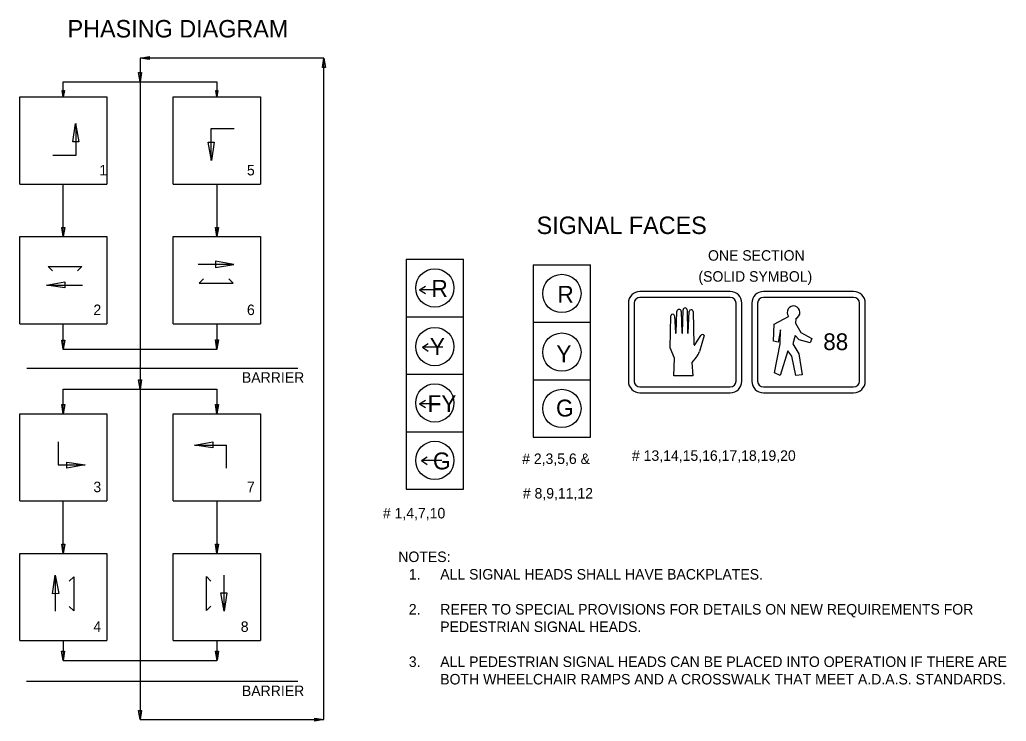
# Model space of a CAD drawing. Extents: x 1 to 35.4, y 0.4 to 10.6.
# Drawn here: x 26.82 to 34.35, y 5.23 to 10.58 of the extents above; entities that cross this region are included whole.
import ezdxf

# ---------------------------------------------------------------- set-up
doc = ezdxf.new("R2010")
doc.units = 0
for name, color, linetype in [('$', 7, 'Continuous'), ('base', 7, 'Continuous'), ('PHASE', 7, 'Continuous'), ('TBLBDR', 7, 'Continuous'), ('TBLTEXT', 7, 'Continuous'), ('TITEXT', 7, 'Continuous')]:
    doc.layers.add(name, color=color, linetype=linetype)

msp = doc.modelspace()

# ---------------------------------------------------------------- linework, layer by layer
at = {"layer": '$'}
for p, q in [((27.1527, 10.1019), (28.3243, 10.1019)), ((28.454, 8.7083), (28.1808, 8.7083)), ((27.025, 8.551), (27.2981, 8.551)), ((27.1147, 7.3563), (27.1147, 7.1812)), ((28.1534, 7.3322), (28.3967, 7.3322)), ((28.3967, 7.1577), (28.3967, 7.3322)), ((27.1147, 7.1812), (27.3197, 7.1812)), ((27.1527, 5.8427), (27.1527, 5.6899))]:
    msp.add_line(p, q, dxfattribs=at)
for points in [[(29.1404, 10.282), (27.7385, 10.282), (27.7385, 10.1019)], [(27.7385, 5.7278), (27.7385, 5.2395), (29.1404, 5.2395), (29.1404, 10.282)], [(27.1527, 9.987), (27.1527, 10.1019)], [(28.3243, 10.1019), (28.3243, 9.987)], [(27.2484, 9.7833), (27.2484, 9.5401), (27.0739, 9.5401)], [(28.2818, 9.5015), (28.2818, 9.7448), (28.4563, 9.7448)], [(27.1527, 8.9222), (27.1527, 9.3225)], [(28.3243, 9.3225), (28.3243, 8.9222)], [(28.3243, 8.2577), (28.3243, 8.0617), (27.1527, 8.0617), (27.1527, 8.2577)], [(27.7385, 8.0617), (27.7385, 7.7592)], [(27.1527, 7.572), (27.1527, 7.7592), (28.3243, 7.7592), (28.3243, 7.572)], [(27.1527, 6.5072), (27.1527, 6.9075)], [(28.3243, 6.9075), (28.3243, 6.5072)], [(27.0919, 6.34), (27.0919, 6.0669)], [(28.3795, 6.0669), (28.3795, 6.34)]]:
    msp.add_lwpolyline(points, dxfattribs=at)
at = {"layer": 'PHASE'}
for p, q in [((29.8702, 8.5159), (29.9152, 8.5442)), ((30.0263, 8.5159), (29.8702, 8.5159)), ((29.8702, 8.5159), (29.9152, 8.4875)), ((29.8917, 8.078), (29.9366, 8.1063)), ((30.0478, 8.078), (29.8917, 8.078)), ((29.8917, 8.078), (29.9366, 8.0496)), ((29.8695, 7.6472), (29.9144, 7.6755)), ((30.0256, 7.6472), (29.8695, 7.6472)), ((29.8695, 7.6472), (29.9144, 7.6188)), ((29.8844, 7.2141), (29.9293, 7.2424)), ((30.0405, 7.2141), (29.8844, 7.2141)), ((29.8844, 7.2141), (29.9293, 7.1857))]:
    msp.add_line(p, q, dxfattribs=at)
for points in [[(31.8754, 8.1885), (31.88, 8.364)], [(31.9106, 8.3643), (31.9146, 8.1878)], [(31.9794, 8.0023), (31.9477, 7.9631), (31.9556, 7.8601), (31.809, 7.8601), (31.8142, 7.9949), (31.7812, 8.0742), (31.7864, 8.3182)], [(31.8147, 8.3185), (31.822, 8.1884)], [(31.8261, 8.1884), (31.8319, 8.3506)], [(31.8665, 8.3517), (31.871, 8.1884)], [(31.9188, 8.1878), (31.9275, 8.3506)], [(31.9564, 8.3517), (31.9627, 8.0985)], [(32.6217, 7.8627), (32.5777, 7.8825), (32.6202, 8.1041), (32.622, 8.21), (32.6064, 8.1182), (32.5697, 8.1239), (32.5759, 8.2545), (32.6847, 8.3136)], [(32.7393, 8.2983), (32.7384, 8.2617), (32.7793, 8.1904), (32.8617, 8.1458), (32.8496, 8.1128), (32.7654, 8.1341), (32.7359, 8.1673), (32.7179, 8.1044), (32.7638, 8.0292), (32.7877, 7.8678), (32.741, 7.864), (32.7104, 8.0102), (32.6802, 8.0499), (32.6217, 7.8627)], [(31.9704, 8.0959), (32.0156, 8.1685)], [(32.0417, 8.1691), (32.0056, 8.0454)]]:
    msp.add_lwpolyline(points, dxfattribs=at)
for centre in [(29.9865, 8.5306), (30.9555, 8.4883), (29.9865, 8.0834), (30.9555, 8.041), (29.9865, 7.654), (30.9555, 7.6116), (29.9865, 7.2156)]:
    msp.add_circle(centre, 0.1461, dxfattribs=at)
for centre, radius, start, end in [((31.8492, 8.3489), 0.0175, 9.19884, 174.46931), ((31.8953, 8.3624), 0.0154, 6.92087, 174.32546), ((31.942, 8.3504), 0.0145, 5.08526, 179.16231), ((32.7227, 8.3443), 0.0489, 289.8249, 219.00652), ((31.8006, 8.3177), 0.0142, 3.29515, 178.19589), ((31.8241, 8.1884), 0.00203, 181.1546, 359.79185), ((31.8732, 8.1885), 0.0022, 181.28856, 2.11272), ((31.9167, 8.188), 0.00213, 183.88454, 355.84434), ((32.0289, 8.1587), 0.0165, 38.81604, 143.75147), ((31.9671, 8.0988), 0.00441, 183.95836, 317.86458), ((31.9141, 8.0715), 0.0951, 313.34065, 344.09332)]:
    msp.add_arc(centre, radius, start, end, dxfattribs=at)
at = {"layer": 'TBLBDR'}
for p, q in [((26.8205, 9.987), (27.485, 9.987)), ((26.8205, 9.3225), (26.8205, 9.987)), ((27.485, 9.987), (27.485, 9.3225)), ((27.992, 9.987), (28.6565, 9.987)), ((27.992, 9.3225), (27.992, 9.987)), ((28.6565, 9.987), (28.6565, 9.3225)), ((26.8205, 9.3225), (27.485, 9.3225)), ((27.992, 9.3225), (28.6565, 9.3225)), ((26.8205, 8.9222), (27.485, 8.9222)), ((26.8205, 8.2577), (26.8205, 8.9222)), ((27.485, 8.9222), (27.485, 8.2577)), ((27.992, 8.2577), (27.992, 8.9222)), ((27.992, 8.9222), (28.6565, 8.9222)), ((28.6565, 8.9222), (28.6565, 8.2577)), ((29.7673, 8.7498), (30.2056, 8.7498)), ((29.7673, 8.7498), (29.7673, 6.9964)), ((30.2056, 6.9964), (30.2056, 8.7498)), ((30.7363, 8.7075), (31.1747, 8.7075)), ((30.7363, 8.7075), (30.7363, 7.3924)), ((31.1747, 7.3924), (31.1747, 8.7075)), ((29.7673, 8.3115), (30.2056, 8.3115)), ((26.8205, 8.2577), (27.485, 8.2577)), ((27.992, 8.2577), (28.6565, 8.2577)), ((30.7363, 8.2691), (31.1747, 8.2691)), ((29.7673, 7.8731), (30.2056, 7.8731)), ((30.7363, 7.8308), (31.1747, 7.8308)), ((26.8205, 7.572), (27.485, 7.572)), ((26.8205, 6.9075), (26.8205, 7.572)), ((27.485, 7.572), (27.485, 6.9075)), ((27.992, 7.572), (28.6565, 7.572)), ((27.992, 6.9075), (27.992, 7.572)), ((28.6565, 7.572), (28.6565, 6.9075)), ((29.7673, 7.4348), (30.2056, 7.4348)), ((30.7363, 7.3924), (31.1747, 7.3924)), ((29.7673, 6.9964), (30.2056, 6.9964)), ((26.8205, 6.9075), (27.485, 6.9075)), ((27.992, 6.9075), (28.6565, 6.9075)), ((26.8205, 5.8427), (26.8205, 6.5072)), ((26.8205, 6.5072), (27.485, 6.5072)), ((27.485, 6.5072), (27.485, 5.8427)), ((27.992, 5.8427), (27.992, 6.5072)), ((27.992, 6.5072), (28.6565, 6.5072)), ((28.6565, 6.5072), (28.6565, 5.8427)), ((26.8205, 5.8427), (27.485, 5.8427)), ((27.992, 5.8427), (28.6565, 5.8427))]:
    msp.add_line(p, q, dxfattribs=at)
for points in [[(32.2397, 8.5032), (31.5514, 8.5032)], [(33.1811, 8.5032), (32.4929, 8.5032)], [(32.2397, 8.4589), (31.5514, 8.4589)], [(33.1811, 8.4589), (32.4929, 8.4589)], [(31.4627, 8.4145), (31.4627, 7.82)], [(31.5071, 8.4145), (31.5071, 7.82)], [(32.284, 7.82), (32.284, 8.4145)], [(32.3284, 7.82), (32.3284, 8.4145)], [(32.4041, 8.4145), (32.4041, 7.82)], [(32.4485, 8.4145), (32.4485, 7.82)], [(33.2255, 7.82), (33.2255, 8.4145)], [(33.2698, 7.82), (33.2698, 8.4145)], [(31.5514, 7.7757), (32.2397, 7.7757)], [(32.4929, 7.7757), (33.1811, 7.7757)], [(31.5514, 7.7313), (32.2397, 7.7313)], [(32.4929, 7.7313), (33.1811, 7.7313)]]:
    msp.add_lwpolyline(points, dxfattribs=at)
for centre, radius, start, end in [((31.5514, 8.4145), 0.0887, 90, 180), ((32.2397, 8.4145), 0.0887, 360, 90), ((32.4929, 8.4145), 0.0887, 90, 180), ((33.1811, 8.4145), 0.0887, 360, 90), ((31.5514, 8.4145), 0.0444, 90, 180), ((32.2397, 8.4145), 0.0444, 360, 90), ((32.4929, 8.4145), 0.0444, 90, 180), ((33.1811, 8.4145), 0.0444, 360, 90), ((31.5514, 7.82), 0.0887, 180, 270), ((31.5514, 7.82), 0.0444, 180, 270), ((32.2397, 7.82), 0.0887, 270, 360), ((32.2397, 7.82), 0.0444, 270, 360), ((32.4929, 7.82), 0.0887, 180, 270), ((32.4929, 7.82), 0.0444, 180, 270), ((33.1811, 7.82), 0.0887, 270, 360), ((33.1811, 7.82), 0.0444, 270, 360)]:
    msp.add_arc(centre, radius, start, end, dxfattribs=at)
at = {"layer": 'TITEXT'}
for p, q in [((26.8752, 7.92), (28.9411, 7.92)), ((28.3243, 5.8427), (28.3243, 5.6899)), ((27.1527, 5.6899), (28.3243, 5.6899)), ((28.9411, 5.5313), (26.8732, 5.5313))]:
    msp.add_line(p, q, dxfattribs=at)
for points in [[(27.8083, 10.2949), (27.8087, 10.2716), (27.7385, 10.282)], [(29.1533, 10.2122), (29.13, 10.2118), (29.1404, 10.282)], [(27.7256, 10.1717), (27.749, 10.1721), (27.7385, 10.1019)], [(27.1446, 10.0361), (27.1609, 10.0361), (27.1527, 9.987)], [(28.3161, 10.0361), (28.3325, 10.0361), (28.3243, 9.987)], [(27.2725, 9.6442), (27.2258, 9.6434), (27.2467, 9.7839)], [(28.2576, 9.6407), (28.3043, 9.6415), (28.2834, 9.501)], [(27.1411, 8.9923), (27.1644, 8.9923), (27.1527, 8.9222)], [(28.3126, 8.9923), (28.336, 8.9923), (28.3243, 8.9222)], [(28.3143, 8.7341), (28.3135, 8.6874), (28.454, 8.7083)], [(27.1646, 8.5769), (27.1654, 8.5302), (27.025, 8.551)], [(27.1411, 8.1333), (27.1644, 8.1333), (27.1527, 8.0633)], [(28.3126, 8.1349), (28.336, 8.1349), (28.3243, 8.0649)], [(27.7257, 7.829), (27.749, 7.8294), (27.7386, 7.7592)], [(27.1411, 7.642), (27.1644, 7.642), (27.1527, 7.572)], [(28.3126, 7.642), (28.336, 7.642), (28.3243, 7.572)], [(28.293, 7.358), (28.2939, 7.3113), (28.1534, 7.3322)], [(27.18, 7.1554), (27.1792, 7.2021), (27.3197, 7.1812)], [(27.1411, 6.5772), (27.1644, 6.5772), (27.1527, 6.5072)], [(28.3126, 6.5772), (28.336, 6.5772), (28.3243, 6.5072)], [(27.1177, 6.2004), (27.071, 6.1996), (27.0919, 6.34)], [(28.3537, 6.2065), (28.4004, 6.2074), (28.3795, 6.0669)], [(27.1398, 5.7604), (27.1632, 5.7608), (27.1527, 5.6906)], [(28.3126, 5.7604), (28.336, 5.7608), (28.3255, 5.6906)], [(27.7256, 5.3093), (27.749, 5.3098), (27.7385, 5.2395)], [(29.0707, 5.2273), (29.0703, 5.2506), (29.1405, 5.2402)]]:
    msp.add_lwpolyline(points, close=True, dxfattribs=at)
for points in [[(27.7385, 10.1019), (27.7385, 8.0617)], [(27.0702, 8.6609), (27.0366, 8.6945), (27.2951, 8.6945), (27.2614, 8.6609)], [(28.223, 8.6011), (28.1894, 8.5675), (28.4479, 8.5675), (28.4142, 8.6011)], [(27.7385, 7.7592), (27.7385, 5.7278)], [(27.1983, 6.294), (27.2319, 6.3276), (27.2319, 6.0691), (27.1983, 6.1027)], [(28.278, 6.105), (28.2444, 6.0713), (28.2444, 6.3298), (28.278, 6.2962)]]:
    msp.add_lwpolyline(points, dxfattribs=at)

# ---------------------------------------------------------------- texts
at = {"layer": '$'}
msp.add_text('PHASING DIAGRAM', height=0.1333, dxfattribs=at).set_placement((27.1854, 10.4398))
at = {"layer": 'base'}
msp.add_text('SIGNAL FACES', height=0.1333, dxfattribs=at).set_placement((30.763, 8.9414))
at = {"layer": 'TBLTEXT'}
for s, height, p in [('1', 0.08, (27.4278, 9.3886)), ('5', 0.08, (28.5537, 9.3886)), ('ONE SECTION ', 0.08, (32.0703, 8.7382)), ('(SOLID SYMBOL)', 0.08, (31.9971, 8.5782)), ('R', 0.1288, (29.9613, 8.4627)), ('R', 0.1288, (30.922, 8.4176)), ('2', 0.08, (27.3822, 8.3238)), ('6', 0.08, (28.5537, 8.3238)), ('Y', 0.1288, (29.9484, 8.0193)), ('88', 0.12774, (32.9493, 8.0566)), ('Y', 0.1288, (30.9134, 7.964)), ('BARRIER', 0.08, (28.5151, 7.8081)), ('FY', 0.12881, (29.931, 7.584)), ('G', 0.1288, (30.9107, 7.5503)), ('G', 0.1288, (29.9724, 7.1473)), ('# 2,3,5,6 &', 0.08, (30.6524, 7.1885)), ('# 13,14,15,16,17,18,19,20', 0.08, (31.49, 7.2125)), ('3', 0.08, (27.3822, 6.9736)), ('7', 0.08, (28.5537, 6.9736)), ('# 8,9,11,12', 0.08, (30.6578, 6.9252)), ('# 1,4,7,10', 0.08, (29.5905, 6.7737)), ('NOTES:', 0.08, (29.7079, 6.4411)), ('1.', 0.08, (29.7879, 6.3078)), ('ALL SIGNAL HEADS SHALL HAVE BACKPLATES.', 0.08, (30.0279, 6.3078)), ('2.', 0.08, (29.7879, 6.0411)), ('REFER TO SPECIAL PROVISIONS FOR DETAILS ON NEW REQUIREMENTS FOR', 0.08, (30.0279, 6.0411)), ('4', 0.08, (27.3822, 5.9088)), ('8', 0.08, (28.5066, 5.9088)), ('PEDESTRIAN SIGNAL HEADS.', 0.08, (30.0279, 5.9078)), ('3.', 0.08, (29.7879, 5.6411)), ('ALL PEDESTRIAN SIGNAL HEADS CAN BE PLACED INTO OPERATION IF THERE ARE', 0.08, (30.0279, 5.6411)), ('BOTH WHEELCHAIR RAMPS AND A CROSSWALK THAT MEET A.D.A.S. STANDARDS.', 0.08, (30.0279, 5.5078)), ('BARRIER', 0.08, (28.5151, 5.4194))]:
    msp.add_text(s, height=height, dxfattribs=at).set_placement(p)

doc.saveas('drawing.dxf')
